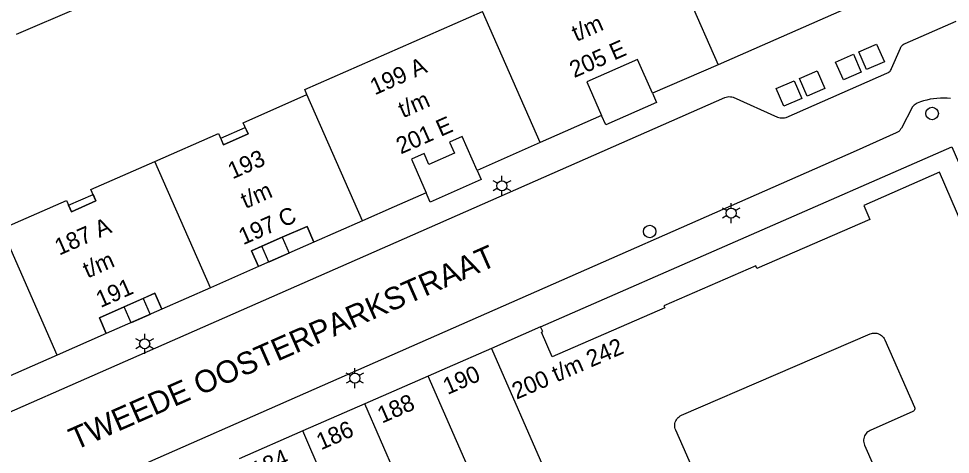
# Model space of a CAD drawing. Extents: x 122462 to 123306, y 485548 to 486417.
# Drawn here: x 123170.2 to 123253.6, y 485664.9 to 485703.9 of the extents above; entities that cross this region are included whole.
import ezdxf

# ---------------------------------------------------------------- set-up
doc = ezdxf.new("R2010")
doc.units = 0
for name, color, linetype in [('Level 1', 7, 'Continuous'), ('Level 10', 7, 'Continuous'), ('Level 11', 7, 'Continuous'), ('Level 17', 7, 'Continuous'), ('Level 19', 7, 'Continuous'), ('Level 30', 7, 'Continuous'), ('Level 4', 7, 'Continuous'), ('Level 42', 7, 'Continuous'), ('Level 50', 7, 'Continuous'), ('Level 53', 7, 'Continuous'), ('Level 58', 7, 'Continuous'), ('Level 59', 7, 'Continuous')]:
    doc.layers.add(name, color=color, linetype=linetype)

msp = doc.modelspace()

# ---------------------------------------------------------------- linework, layer by layer
at = {"layer": 'Level 1'}
for p, q in [((123193.741, 485684.349), (123191.936, 485683.554)), ((123181.302, 485678.873), (123179.607, 485678.127)), ((123216.88, 485676.329), (123212.469, 485674.4)), ((123206.815, 485671.929), (123201.138, 485669.447)), ((123201.138, 485669.447), (123195.582, 485667.019)), ((123195.582, 485667.019), (123189.89, 485664.529))]:
    msp.add_line(p, q, dxfattribs=at)
for points in [[(123253.528, 485722.014), (123254.249, 485722.329), (123259.059, 485711.38), (123232.769, 485699.799)], [(123195.968, 485697.128), (123195.767, 485697.586), (123211.681, 485704.573)], [(123232.769, 485699.799), (123226.881, 485697.245), (123225.55, 485700.268), (123221.006, 485698.268), (123222.337, 485695.245), (123216.851, 485692.83)], [(123182.346, 485691.132), (123188.061, 485693.648), (123188.505, 485692.641), (123190.692, 485693.604), (123190.249, 485694.61), (123195.968, 485697.128)], [(123216.851, 485692.83), (123211.197, 485690.341), (123209.866, 485693.363), (123208.723, 485692.86), (123209.158, 485691.873), (123206.888, 485690.874), (123206.454, 485691.861), (123205.309, 485691.357), (123206.639, 485688.334), (123203.784, 485687.077), (123200.929, 485685.819)], [(123168.646, 485685.1), (123174.435, 485687.649), (123174.878, 485686.642), (123177.074, 485687.609), (123176.631, 485688.616), (123182.346, 485691.132)], [(123260.191, 485673.746), (123260.119, 485673.911), (123259.122, 485673.477), (123255.696, 485681.362), (123256.289, 485681.62), (123252.57, 485690.17), (123245.799, 485687.199), (123246.351, 485685.947), (123236.239, 485681.543), (123236.13, 485681.789), (123227.91, 485678.209), (123227.989, 485678.03), (123217.928, 485673.648), (123216.959, 485675.858), (123217.067, 485675.905), (123216.88, 485676.329)], [(123200.929, 485685.819), (123196.595, 485683.911), (123195.97, 485685.33), (123193.741, 485684.349)], [(123191.936, 485683.554), (123190.997, 485683.141), (123191.622, 485681.722), (123187.322, 485679.829)], [(123187.322, 485679.829), (123182.975, 485677.915), (123182.35, 485679.334), (123181.302, 485678.873)], [(123179.607, 485678.127), (123177.382, 485677.147), (123178.006, 485675.728), (123173.62, 485673.799)], [(123230.82, 485662.891), (123228.968, 485667.091), (123228.926, 485667.205), (123228.898, 485667.323), (123228.884, 485667.444), (123228.885, 485667.565), (123228.901, 485667.685), (123228.932, 485667.803), (123228.976, 485667.916), (123229.034, 485668.023), (123229.104, 485668.122), (123229.186, 485668.212), (123229.278, 485668.291), (123229.379, 485668.358), (123229.487, 485668.413), (123246.37, 485675.698), (123246.483, 485675.739), (123246.6, 485675.766), (123246.719, 485675.779), (123246.839, 485675.777), (123246.959, 485675.761), (123247.075, 485675.731), (123247.187, 485675.687), (123247.292, 485675.631), (123247.391, 485675.561), (123247.48, 485675.481), (123247.559, 485675.39), (123247.626, 485675.291), (123247.681, 485675.184), (123250.347, 485669.138), (123250.37, 485669.057), (123250.371, 485668.98), (123250.352, 485668.905), (123250.314, 485668.838), (123250.26, 485668.782), (123250.194, 485668.742), (123246.389, 485667.064), (123246.282, 485667.009), (123246.182, 485666.941), (123246.091, 485666.862), (123246.01, 485666.772), (123245.941, 485666.673), (123245.884, 485666.567), (123245.84, 485666.454), (123245.81, 485666.337), (123245.795, 485666.217), (123245.794, 485666.097), (123245.807, 485665.977), (123245.835, 485665.859), (123245.877, 485665.746), (123247.599, 485661.841)], [(123212.469, 485674.4), (123208.503, 485672.667), (123206.815, 485671.929)], [(123173.62, 485673.799), (123169.145, 485671.826), (123168.519, 485673.245), (123166.299, 485672.265)]]:
    msp.add_lwpolyline(points, dxfattribs=at)
at = {"layer": 'Level 10'}
for points in [[(123188.505, 485692.641), (123188.251, 485693.217), (123190.438, 485694.181), (123190.692, 485693.604), (123188.505, 485692.641)], [(123174.878, 485686.642), (123174.625, 485687.219), (123176.82, 485688.186), (123177.074, 485687.609), (123174.878, 485686.642)], [(123191.622, 485681.722), (123190.997, 485683.141), (123193.741, 485684.349), (123195.97, 485685.33), (123196.595, 485683.911), (123191.622, 485681.722)], [(123178.006, 485675.728), (123177.382, 485677.147), (123179.607, 485678.127), (123182.35, 485679.334), (123182.975, 485677.915), (123178.006, 485675.728)]]:
    msp.add_lwpolyline(points, dxfattribs=at)
at = {"layer": 'Level 11'}
for points in [[(123226.881, 485697.245), (123227.248, 485696.413), (123222.704, 485694.413), (123222.337, 485695.245)], [(123211.197, 485690.341), (123211.564, 485689.509), (123207.006, 485687.502), (123206.639, 485688.334)]]:
    msp.add_lwpolyline(points, dxfattribs=at)
at = {"layer": 'Level 17'}
for points in [[(123249.112, 485701.355), (123249.153, 485701.432), (123249.205, 485701.502), (123249.266, 485701.563), (123249.336, 485701.615), (123249.413, 485701.656), (123249.495, 485701.686), (123254.088, 485703.694)], [(123140.615, 485656.071), (123204.708, 485684.255), (123233.363, 485696.855), (123233.485, 485696.897), (123233.61, 485696.925), (123233.739, 485696.939), (123233.867, 485696.937), (123233.995, 485696.92), (123234.12, 485696.888), (123238.081, 485695.115), (123238.204, 485695.073), (123238.331, 485695.045), (123238.46, 485695.032), (123238.59, 485695.035), (123238.719, 485695.052), (123238.845, 485695.084), (123247.858, 485699.028), (123247.942, 485699.06), (123248.02, 485699.102), (123248.092, 485699.156), (123248.156, 485699.218), (123248.21, 485699.289), (123248.255, 485699.367), (123248.288, 485699.45), (123249.082, 485701.273), (123249.112, 485701.355)], [(123253.575, 485696.774), (123253.271, 485696.8), (123252.966, 485696.81), (123252.661, 485696.805), (123252.356, 485696.785), (123252.053, 485696.751), (123251.752, 485696.701), (123251.453, 485696.636), (123251.159, 485696.556), (123250.868, 485696.462), (123250.583, 485696.354), (123250.487, 485696.303), (123250.397, 485696.244), (123250.313, 485696.176), (123250.236, 485696.1), (123250.167, 485696.017), (123249.172, 485694.124), (123249.103, 485694.017), (123249.022, 485693.92), (123248.93, 485693.833), (123248.827, 485693.758), (123248.716, 485693.697), (123245.123, 485692.101), (123207.552, 485675.569), (123168.357, 485658.322)], [(123216.88, 485676.329), (123253.699, 485692.444), (123261.572, 485674.346)]]:
    msp.add_lwpolyline(points, dxfattribs=at)
at = {"layer": 'Level 19'}
msp.add_line((123175.517, 485704.881), (123169.952, 485702.51), dxfattribs=at)
at = {"layer": 'Level 30'}
for points in [[(123193.741, 485684.349), (123194.365, 485682.93), (123192.561, 485682.135), (123191.936, 485683.554)], [(123181.302, 485678.873), (123181.927, 485677.454), (123180.232, 485676.708), (123179.607, 485678.127)]]:
    msp.add_lwpolyline(points, dxfattribs=at)
at = {"layer": 'Level 4'}
for p, q in [((123227.595, 485711.561), (123232.769, 485699.799)), ((123216.851, 485692.83), (123211.681, 485704.573)), ((123200.929, 485685.819), (123195.968, 485697.128)), ((123187.322, 485679.829), (123182.346, 485691.132)), ((123173.62, 485673.799), (123168.646, 485685.1)), ((123212.469, 485674.4), (123219.524, 485658.311)), ((123212.075, 485659.926), (123206.815, 485671.929)), ((123208.194, 485653.347), (123201.138, 485669.447)), ((123200.847, 485655.005), (123195.582, 485667.019))]:
    msp.add_line(p, q, dxfattribs=at)
at = {"layer": 'Level 42'}
for points in [[(123246.05, 485699.36), (123245.356, 485700.959), (123246.955, 485701.653), (123247.649, 485700.054), (123246.05, 485699.36)], [(123243.982, 485698.442), (123243.281, 485700.039), (123244.878, 485700.74), (123245.579, 485699.143), (123243.982, 485698.442)], [(123240.733, 485696.975), (123240.038, 485698.57), (123241.633, 485699.265), (123242.328, 485697.67), (123240.733, 485696.975)], [(123238.664, 485696.079), (123237.978, 485697.671), (123239.57, 485698.357), (123240.256, 485696.765), (123238.664, 485696.079)]]:
    msp.add_lwpolyline(points, dxfattribs=at)
at = {"layer": 'Level 50'}
for p, q in [((123213.03, 485689.184), (123212.64, 485689.409)), ((123213.42, 485689.409), (123213.42, 485689.859)), ((123214.199, 485689.409), (123213.809, 485689.184)), ((123213.03, 485688.734), (123212.64, 485688.509)), ((123213.42, 485688.059), (123213.42, 485688.509)), ((123214.199, 485688.509), (123213.809, 485688.734)), ((123233.55, 485686.744), (123233.16, 485686.969)), ((123233.94, 485686.969), (123233.94, 485687.419)), ((123234.719, 485686.969), (123234.329, 485686.744)), ((123233.55, 485686.294), (123233.16, 485686.069)), ((123233.94, 485685.619), (123233.94, 485686.069)), ((123234.719, 485686.069), (123234.329, 485686.294)), ((123181.05, 485675.044), (123180.66, 485675.269)), ((123181.44, 485675.269), (123181.44, 485675.719)), ((123182.219, 485675.269), (123181.829, 485675.044)), ((123181.05, 485674.594), (123180.66, 485674.369)), ((123181.44, 485673.919), (123181.44, 485674.369)), ((123182.219, 485674.369), (123181.829, 485674.594)), ((123200.26, 485672.189), (123200.26, 485672.639)), ((123199.87, 485671.964), (123199.48, 485672.189)), ((123201.039, 485672.189), (123200.649, 485671.964)), ((123199.87, 485671.514), (123199.48, 485671.289)), ((123200.26, 485670.839), (123200.26, 485671.289)), ((123201.039, 485671.289), (123200.649, 485671.514))]:
    msp.add_line(p, q, dxfattribs=at)
for centre in [(123213.42, 485688.959), (123233.94, 485686.519), (123181.44, 485674.819), (123200.26, 485671.739)]:
    msp.add_circle(centre, 0.45, dxfattribs=at)
at = {"layer": 'Level 53'}
for centre in [(123251.92, 485695.429), (123226.643, 485684.871)]:
    msp.add_circle(centre, 0.56, dxfattribs=at)

# ---------------------------------------------------------------- texts
at = {"layer": 'Level 58'}
for s, rotation, p in [('t/m', 23.76108, (123220.084, 485701.839)), ('205 E', 23.76108, (123219.883, 485698.594)), ('199 A', 23.76108, (123202.03, 485697.05)), ('t/m', 23.76108, (123204.559, 485695.005)), ('201 E', 23.76108, (123204.359, 485691.76)), ('193', 23.76076, (123189.3, 485689.529)), ('t/m', 23.76076, (123190.457, 485686.881)), ('197 C', 23.76076, (123190.258, 485683.636)), ('187 A', 23.76076, (123173.796, 485682.705)), ('t/m', 23.76076, (123176.325, 485680.66)), ('191', 23.76076, (123177.493, 485678.017)), ('200 t/m 242', 23.39876, (123214.722, 485669.809)), ('190', 23.61114, (123208.55, 485670.231)), ('188', 23.61114, (123202.682, 485667.665)), ('186', 23.61114, (123197.221, 485665.279)), ('184', 23.78899, (123191.404, 485662.73))]:
    msp.add_text(s, height=1.5, rotation=rotation, dxfattribs=at).set_placement(p)
at = {"layer": 'Level 59'}
msp.add_text('TWEEDE OOSTERPARKSTRAAT', height=2, rotation=23.73502, dxfattribs=at).set_placement((123175.228, 485665.261))

doc.saveas('drawing.dxf')
